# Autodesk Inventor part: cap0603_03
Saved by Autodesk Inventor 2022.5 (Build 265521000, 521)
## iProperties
Created: 2024-12
Part Number: cap0603_03
Material: Generic
Document SubType Name: Modeling
Designer: AdminForWorker
Density: 1 g/cm^3
Appearance: Default
Title: cap0603_03 v1
Author: AdminForWorker
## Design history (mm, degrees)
feature "Body6"
feature "Body8"
feature "Body18"
body "Solid1"
body "Solid2"
body "Solid3"
